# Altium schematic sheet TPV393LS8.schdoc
size 127 x 101 mm
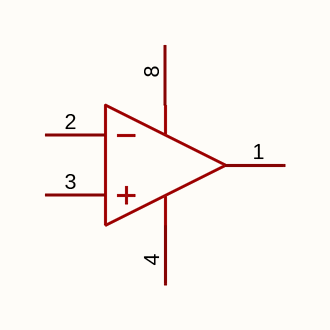
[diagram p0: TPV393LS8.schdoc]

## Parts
U?  tpv393ls8  [SOP-8_L4.9-W3.9-P1.27-LS6.0-BL]  (value not drawn)  (part A of 2)

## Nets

Not connected (* = marked no-connect by the designer): U? 1(OUTA) 2(INA-) 3(INA+) 4(-VS) 8(+VS)

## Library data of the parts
U? = tpv393ls8: 比较器数:双路;输入失调电压(Vos):800uV;输入偏置电流(Ib):2pA;轨到轨:-;; Manufacturer: TECH PUBLIC(台舟); AddInBom: yes; ModelId: 75c24a7891ee4dd6bdac16a7163ff87e; ModelName: SOP-8_L4.9-W3.9-P1.27-LS6.0-BL-1; ModelTransform: 192.913,236.22,0,0,0,0,-0.393,2.749,0; Number of Channels: 双路; Vos - Input Offset Voltage: 800uV; Ib - Input Bias Current: 2pA; Propagation Delay Time: 460ns; Output Type: 开漏; Quiescent Current: 50uA; Maximum Power Supply Range (Vdd-Vss): 7V; Single Supply: 1.8V~5.5V; Input Offset Voltage Drift(Vos TC): 0.8uV/℃; Input Offset Current(Ios): 1pA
